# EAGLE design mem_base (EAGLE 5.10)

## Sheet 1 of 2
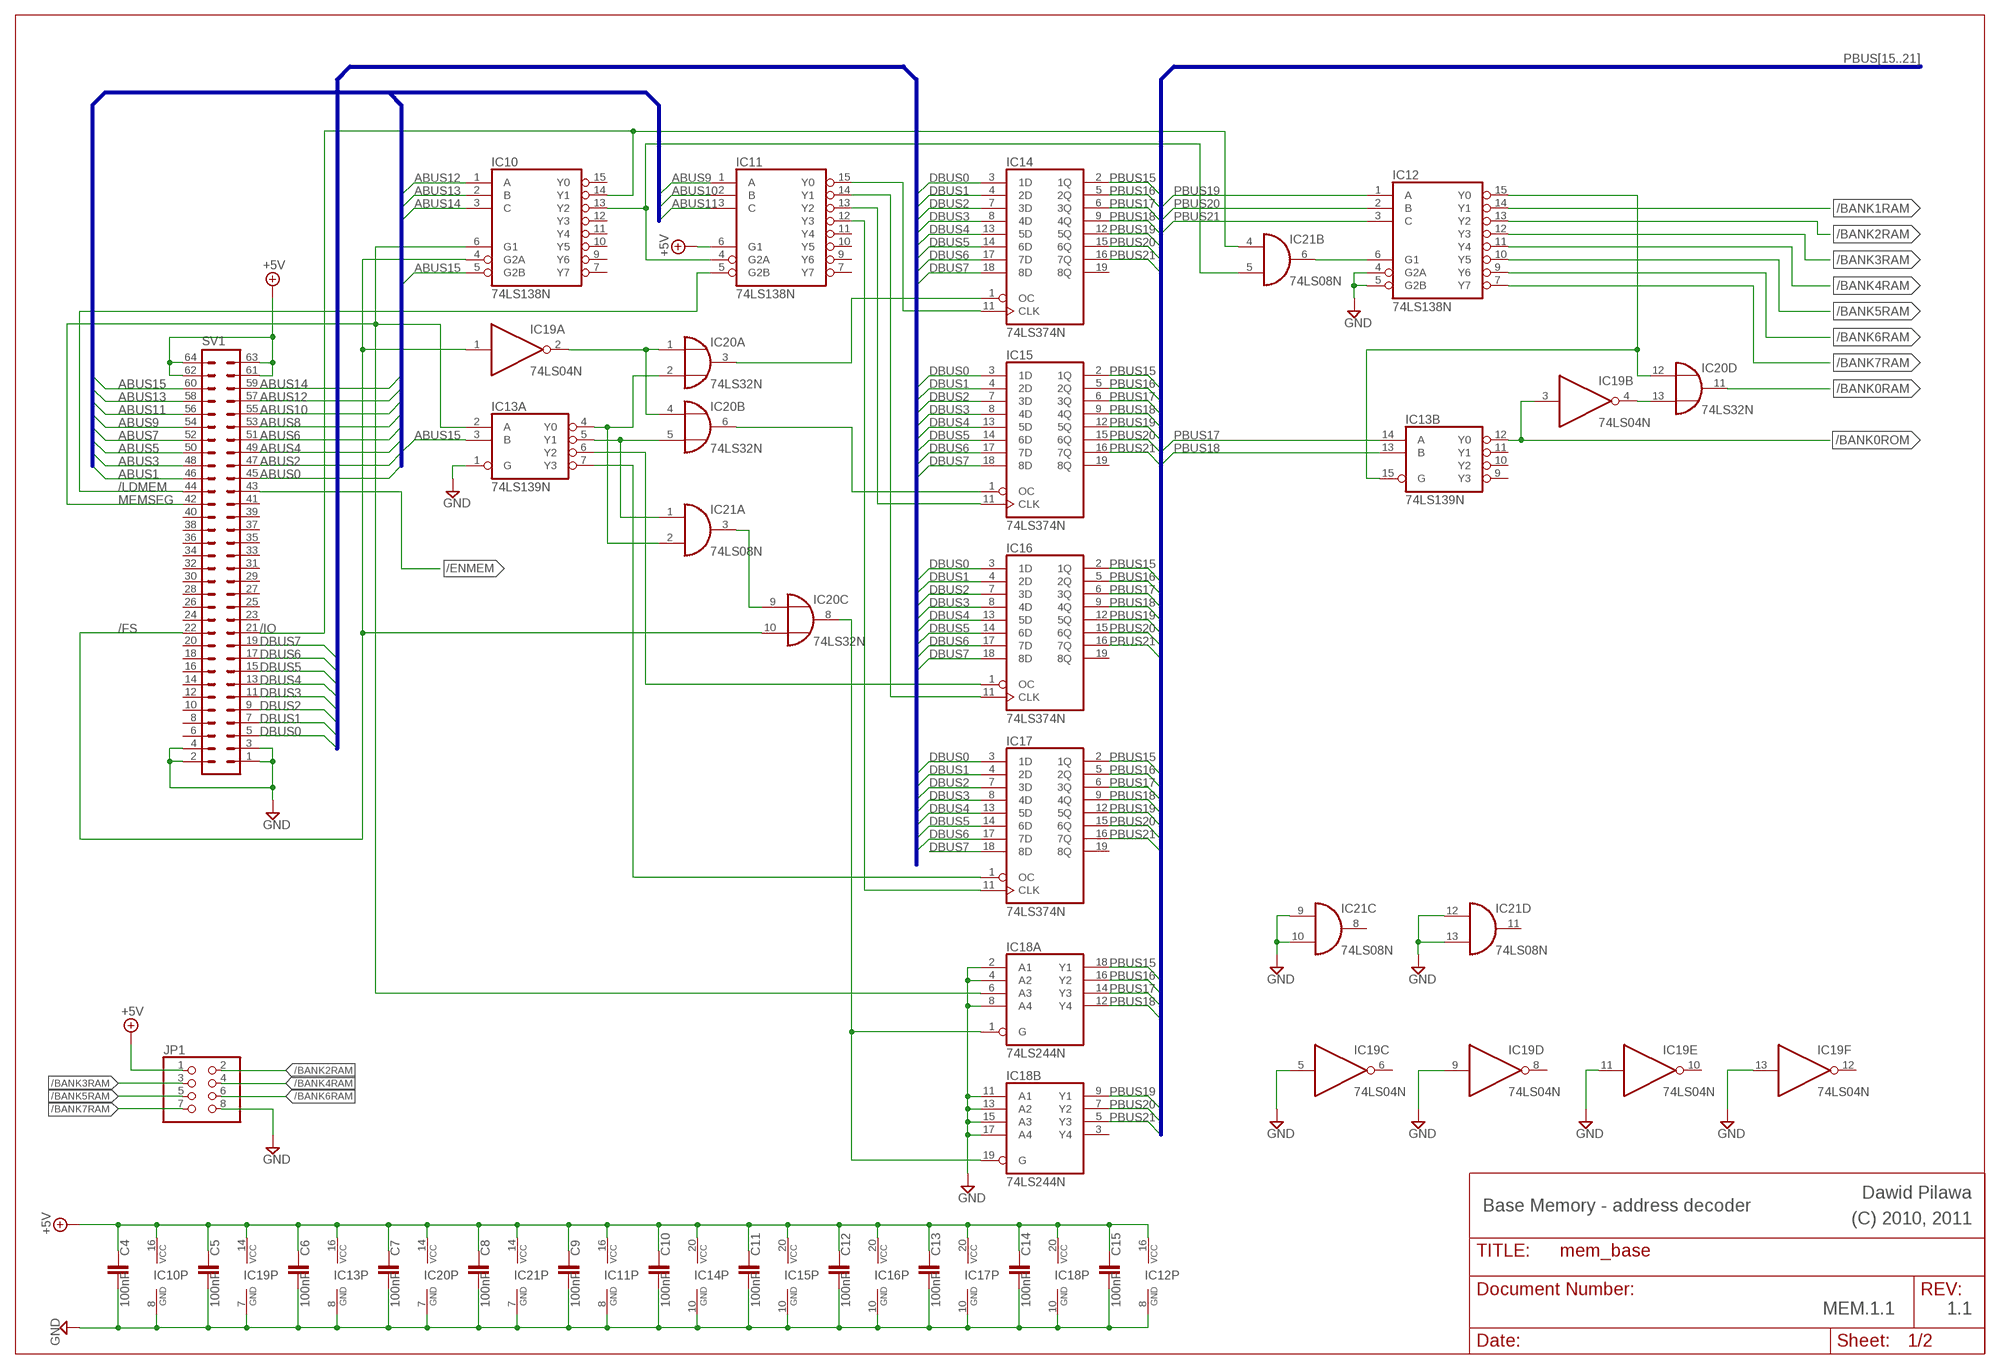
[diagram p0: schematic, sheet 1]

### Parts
C4  100nF  C-EU025-025X050  [C025-025X050]
C5  100nF  C-EU025-025X050  [C025-025X050]
C6  100nF  C-EU025-025X050  [C025-025X050]
C7  100nF  C-EU025-025X050  [C025-025X050]
C8  100nF  C-EU025-025X050  [C025-025X050]
C9  100nF  C-EU025-025X050  [C025-025X050]
C10  100nF  C-EU025-025X050  [C025-025X050]
C11  100nF  C-EU025-025X050  [C025-025X050]
C12  100nF  C-EU025-025X050  [C025-025X050]
C13  100nF  C-EU025-025X050  [C025-025X050]
C14  100nF  C-EU025-025X050  [C025-025X050]
C15  100nF  C-EU025-025X050  [C025-025X050]
IC10  74LS138N  [DIL16]
IC11  74LS138N  [DIL16]
IC12  74LS138N  [DIL16]
IC13  74LS139N  [DIL16]
IC14  74LS374N  [DIL20]
IC15  74LS374N  [DIL20]
IC16  74LS374N  [DIL20]
IC17  74LS374N  [DIL20]
IC18  74LS244N  [DIL20]
IC19  74LS04N  [DIL14]
IC20  74LS32N  [DIL14]
IC21  74LS08N  [DIL14]
JP1  PINHD-2X4  [2X04]
SV1  ML64L  [ML64L]

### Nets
+5V: C4.1 C5.1 C6.1 C7.1 C8.1 C9.1 C10.1 C11.1 C12.1 C13.1 C14.1 C15.1 IC10.16(VCC) IC11.6(G1) IC11.16(VCC) IC12.16(VCC) IC13.16(P:VCC) IC14.20(VCC) IC15.20(VCC) IC16.20(VCC) IC17.20(VCC) IC18.20(P:VCC) IC19.14(P:VCC) IC20.14(P:VCC) IC21.14(P:VCC) JP1.1 SV1.61 SV1.62 SV1.63 SV1.64 ; also sheet 2
/BANK0RAM: IC20.11(D:O) ; also sheet 2
/BANK0ROM: IC13.12(B:Y0) IC19.3(B:I) ; also sheet 2
/BANK1RAM: IC12.14(Y1) ; also sheet 2
/BANK2RAM: IC12.13(Y2) JP1.2
/BANK3RAM: IC12.12(Y3) JP1.3
/BANK4RAM: IC12.11(Y4) JP1.4
/BANK5RAM: IC12.10(Y5) JP1.5
/BANK6RAM: IC12.9(Y6) JP1.6
/BANK7RAM: IC12.7(Y7) JP1.7
/ENMEM: SV1.43 ; also sheet 2
/FS: IC10.4(G2A) IC19.1(A:I) IC20.10(C:I1) SV1.22
/IO: IC10.14(Y1) IC21.4(B:I0) SV1.21
/LDMEM: IC11.5(G2B) SV1.44 ; also sheet 2
ABUS0: SV1.45 ; also sheet 2
ABUS1: SV1.46 ; also sheet 2
ABUS2: SV1.47 ; also sheet 2
ABUS3: SV1.48 ; also sheet 2
ABUS4: SV1.49 ; also sheet 2
ABUS5: SV1.50 ; also sheet 2
ABUS6: SV1.51 ; also sheet 2
ABUS7: SV1.52 ; also sheet 2
ABUS8: SV1.53 ; also sheet 2
ABUS9: IC11.1(A) SV1.54 ; also sheet 2
ABUS10: IC11.2(B) SV1.55 ; also sheet 2
ABUS11: IC11.3(C) SV1.56 ; also sheet 2
ABUS12: IC10.1(A) SV1.57 ; also sheet 2
ABUS13: IC10.2(B) SV1.58 ; also sheet 2
ABUS14: IC10.3(C) SV1.59 ; also sheet 2
ABUS15: IC10.5(G2B) IC13.3(A:B) SV1.60
DBUS0: IC14.3(1D) IC15.3(1D) IC16.3(1D) IC17.3(1D) SV1.5 ; also sheet 2
DBUS1: IC14.4(2D) IC15.4(2D) IC16.4(2D) IC17.4(2D) SV1.7 ; also sheet 2
DBUS2: IC14.7(3D) IC15.7(3D) IC16.7(3D) IC17.7(3D) SV1.9 ; also sheet 2
DBUS3: IC14.8(4D) IC15.8(4D) IC16.8(4D) IC17.8(4D) SV1.11 ; also sheet 2
DBUS4: IC14.13(5D) IC15.13(5D) IC16.13(5D) IC17.13(5D) SV1.13 ; also sheet 2
DBUS5: IC14.14(6D) IC15.14(6D) IC16.14(6D) IC17.14(6D) SV1.15 ; also sheet 2
DBUS6: IC14.17(7D) IC15.17(7D) IC16.17(7D) IC17.17(7D) SV1.17 ; also sheet 2
DBUS7: IC14.18(8D) IC15.18(8D) IC16.18(8D) IC17.18(8D) SV1.19 ; also sheet 2
GND: C4.2 C5.2 C6.2 C7.2 C8.2 C9.2 C10.2 C11.2 C12.2 C13.2 C14.2 C15.2 IC10.8(GND) IC11.8(GND) IC12.4(G2A) IC12.5(G2B) IC12.8(GND) IC13.1(A:G) IC13.8(P:GND) IC14.10(GND) IC15.10(GND) IC16.10(GND) IC17.10(GND) IC18.2(A:A1) IC18.4(A:A2) IC18.8(A:A4) IC18.10(P:GND) IC18.11(B:A1) IC18.13(B:A2) IC18.15(B:A3) IC18.17(B:A4) IC19.5(C:I) IC19.7(P:GND) IC19.9(D:I) IC19.11(E:I) IC19.13(F:I) IC20.7(P:GND) IC21.7(P:GND) IC21.9(C:I0) IC21.10(C:I1) IC21.12(D:I0) IC21.13(D:I1) JP1.8 SV1.1 SV1.2 SV1.3 SV1.4 ; also sheet 2
MEMSEG: IC10.6(G1) IC13.2(A:A) IC18.6(A:A3) SV1.42
N$1: IC10.13(Y2) IC11.4(G2A) IC21.5(B:I1)
N$2: IC19.2(A:O) IC20.1(A:I0) IC20.4(B:I0)
N$3: IC13.4(A:Y0) IC20.2(A:I1) IC21.2(A:I1)
N$4: IC13.5(A:Y1) IC20.5(B:I1) IC21.1(A:I0)
N$5: IC11.15(Y0) IC14.11(CLK)
N$6: IC11.14(Y1) IC16.11(CLK)
N$7: IC11.13(Y2) IC15.11(CLK)
N$8: IC11.12(Y3) IC17.11(CLK)
N$9: IC14.1(OC) IC20.3(A:O)
N$10: IC15.1(OC) IC20.6(B:O)
N$11: IC13.6(A:Y2) IC16.1(OC)
N$12: IC13.7(A:Y3) IC17.1(OC)
N$13: IC18.1(A:G) IC18.19(B:G) IC20.8(C:O)
N$14: IC20.9(C:I0) IC21.3(A:O)
N$15: IC12.15(Y0) IC13.15(B:G) IC20.12(D:I0)
N$16: IC12.6(G1) IC21.6(B:O)
N$17: IC19.4(B:O) IC20.13(D:I1)
PBUS15: IC14.2(1Q) IC15.2(1Q) IC16.2(1Q) IC17.2(1Q) IC18.18(A:Y1) ; also sheet 2
PBUS16: IC14.5(2Q) IC15.5(2Q) IC16.5(2Q) IC17.5(2Q) IC18.16(A:Y2) ; also sheet 2
PBUS17: IC13.14(B:A) IC14.6(3Q) IC15.6(3Q) IC16.6(3Q) IC17.6(3Q) IC18.14(A:Y3) ; also sheet 2
PBUS18: IC13.13(B:B) IC14.9(4Q) IC15.9(4Q) IC16.9(4Q) IC17.9(4Q) IC18.12(A:Y4) ; also sheet 2
PBUS19: IC12.1(A) IC14.12(5Q) IC15.12(5Q) IC16.12(5Q) IC17.12(5Q) IC18.9(B:Y1)
PBUS20: IC12.2(B) IC14.15(6Q) IC15.15(6Q) IC16.15(6Q) IC17.15(6Q) IC18.7(B:Y2)
PBUS21: IC12.3(C) IC14.16(7Q) IC15.16(7Q) IC16.16(7Q) IC17.16(7Q) IC18.5(B:Y3)
Unconnected: IC10.7(Y7) IC10.9(Y6) IC10.10(Y5) IC10.11(Y4) IC10.12(Y3) IC10.15(Y0) IC11.7(Y7) IC11.9(Y6) IC11.10(Y5) IC11.11(Y4) IC13.9(B:Y3) IC13.10(B:Y2) IC13.11(B:Y1) IC14.19(8Q) IC15.19(8Q) IC16.19(8Q) IC17.19(8Q) IC18.3(B:Y4) IC19.6(C:O) IC19.8(D:O) IC19.10(E:O) IC19.12(F:O) IC21.8(C:O) IC21.11(D:O) SV1.6 SV1.8 SV1.10 SV1.12 SV1.14 SV1.16 SV1.18 SV1.20 SV1.23 SV1.24 SV1.25 SV1.26 SV1.27 SV1.28 SV1.29 SV1.30 SV1.31 SV1.32 SV1.33 SV1.34 SV1.35 SV1.36 SV1.37 SV1.38 SV1.39 SV1.40 SV1.41

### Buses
ABUS[0..15]
DBUS[0..7]
PBUS[15..21]

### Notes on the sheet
- Dawid Pilawa
- Base Memory - address decoder | (C) 2010, 2011
- MEM.1.1 | 1.1

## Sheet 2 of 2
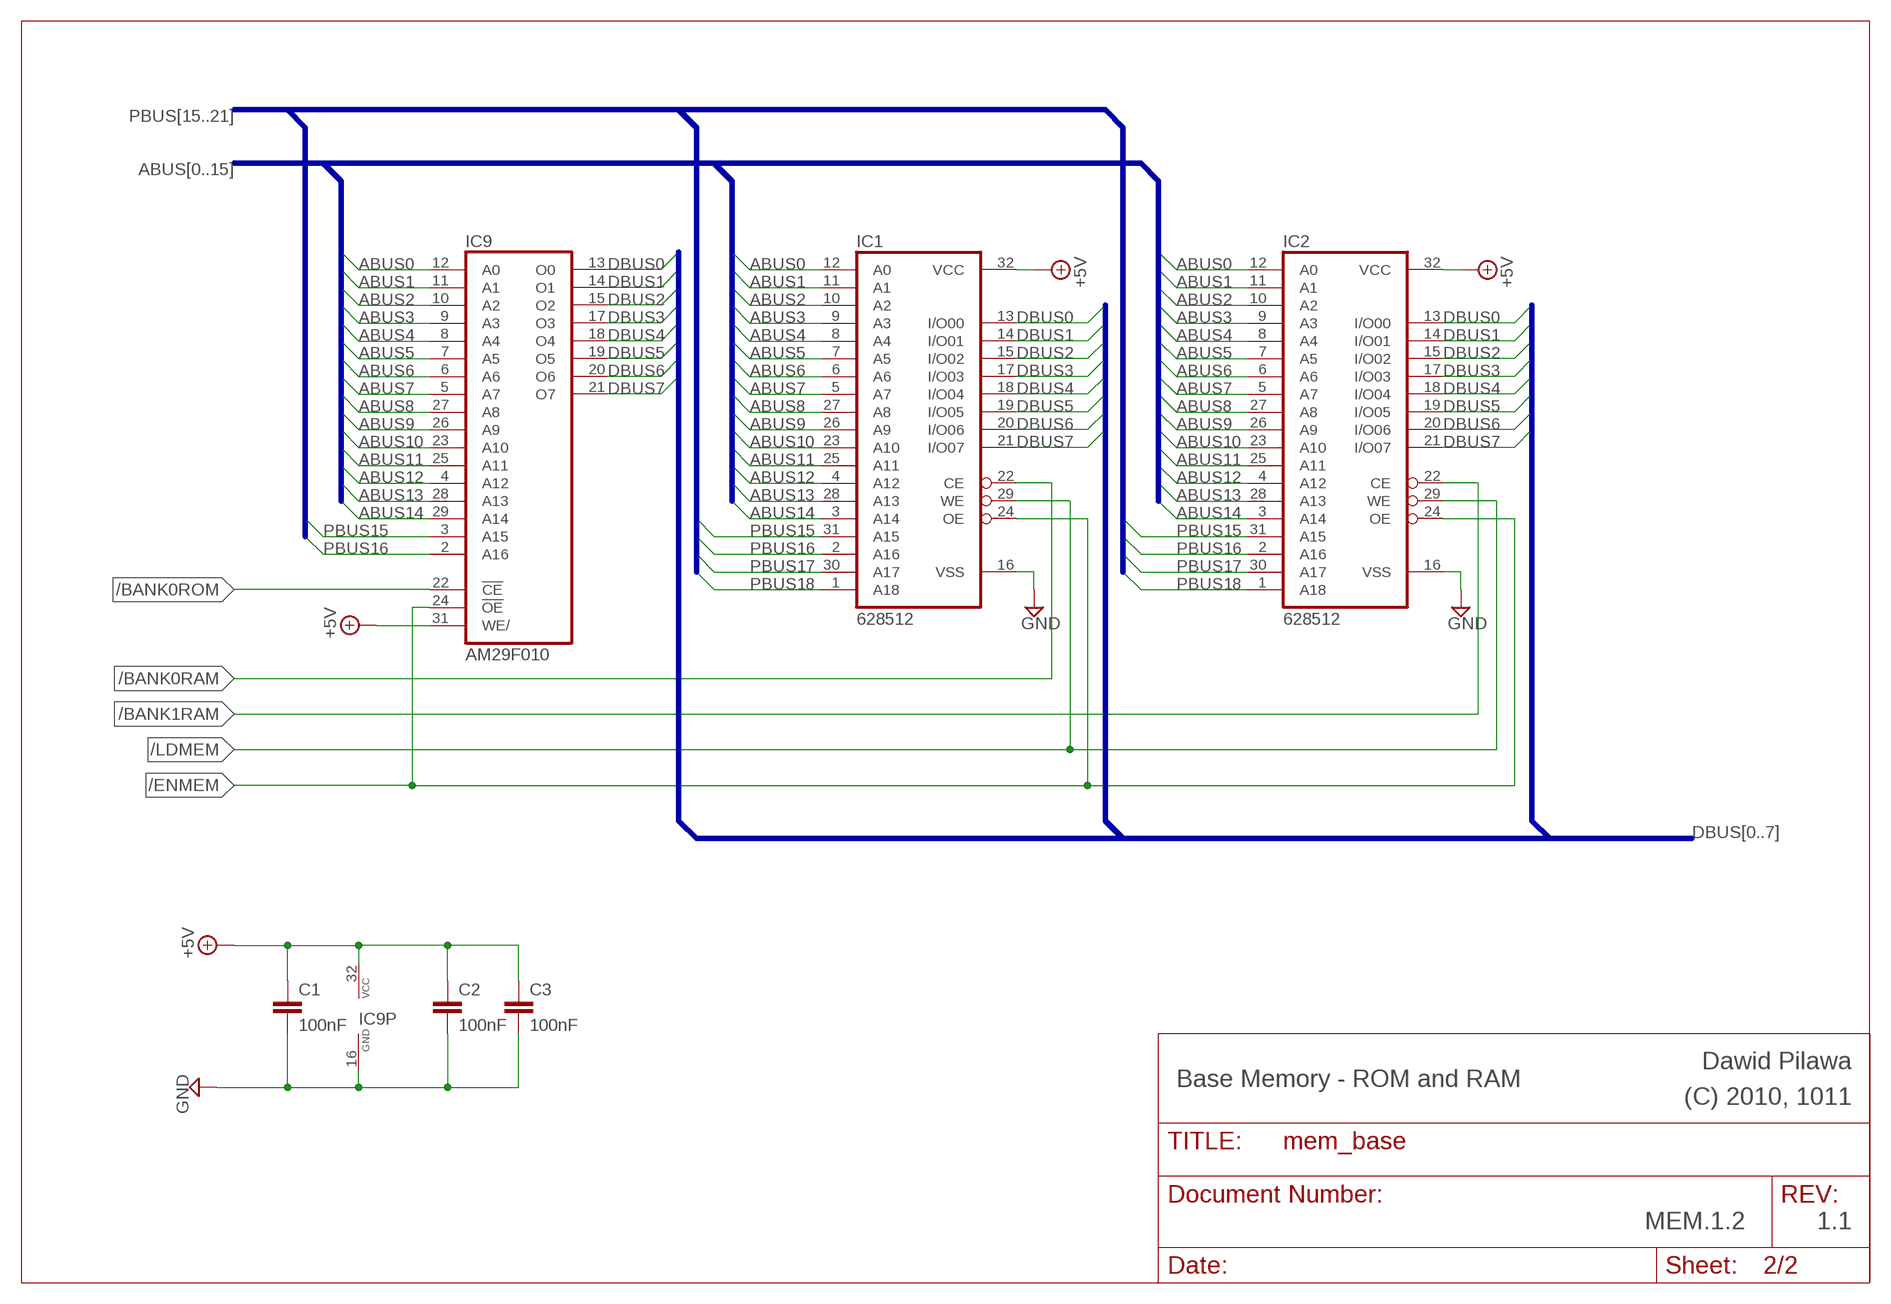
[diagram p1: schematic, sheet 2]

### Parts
C1  100nF  C-EU025-025X050  [C025-025X050]
C2  100nF  C-EU025-025X050  [C025-025X050]
C3  100nF  C-EU025-025X050  [C025-025X050]
IC1  628512  HM628512A_DIL32  [DIL32]
IC2  628512  HM628512A_DIL32  [DIL32]
IC9  AM29F010  [DIL32-6]

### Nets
+5V: C1.1 C2.1 C3.1 IC1.32(VCC) IC2.32(VCC) IC9.31(WE/) IC9.32(VCC) ; also sheet 1
/BANK0RAM: IC1.22(CE) ; also sheet 1
/BANK0ROM: IC9.22(!CE) ; also sheet 1
/BANK1RAM: IC2.22(CE) ; also sheet 1
/ENMEM: IC1.24(OE) IC2.24(OE) IC9.24(!OE) ; also sheet 1
/LDMEM: IC1.29(WE) IC2.29(WE) ; also sheet 1
ABUS0: IC1.12(A0) IC2.12(A0) IC9.12(A0) ; also sheet 1
ABUS1: IC1.11(A1) IC2.11(A1) IC9.11(A1) ; also sheet 1
ABUS2: IC1.10(A2) IC2.10(A2) IC9.10(A2) ; also sheet 1
ABUS3: IC1.9(A3) IC2.9(A3) IC9.9(A3) ; also sheet 1
ABUS4: IC1.8(A4) IC2.8(A4) IC9.8(A4) ; also sheet 1
ABUS5: IC1.7(A5) IC2.7(A5) IC9.7(A5) ; also sheet 1
ABUS6: IC1.6(A6) IC2.6(A6) IC9.6(A6) ; also sheet 1
ABUS7: IC1.5(A7) IC2.5(A7) IC9.5(A7) ; also sheet 1
ABUS8: IC1.27(A8) IC2.27(A8) IC9.27(A8) ; also sheet 1
ABUS9: IC1.26(A9) IC2.26(A9) IC9.26(A9) ; also sheet 1
ABUS10: IC1.23(A10) IC2.23(A10) IC9.23(A10) ; also sheet 1
ABUS11: IC1.25(A11) IC2.25(A11) IC9.25(A11) ; also sheet 1
ABUS12: IC1.4(A12) IC2.4(A12) IC9.4(A12) ; also sheet 1
ABUS13: IC1.28(A13) IC2.28(A13) IC9.28(A13) ; also sheet 1
ABUS14: IC1.3(A14) IC2.3(A14) IC9.29(A14) ; also sheet 1
DBUS0: IC1.13(I/O00) IC2.13(I/O00) IC9.13(O0) ; also sheet 1
DBUS1: IC1.14(I/O01) IC2.14(I/O01) IC9.14(O1) ; also sheet 1
DBUS2: IC1.15(I/O02) IC2.15(I/O02) IC9.15(O2) ; also sheet 1
DBUS3: IC1.17(I/O03) IC2.17(I/O03) IC9.17(O3) ; also sheet 1
DBUS4: IC1.18(I/O04) IC2.18(I/O04) IC9.18(O4) ; also sheet 1
DBUS5: IC1.19(I/O05) IC2.19(I/O05) IC9.19(O5) ; also sheet 1
DBUS6: IC1.20(I/O06) IC2.20(I/O06) IC9.20(O6) ; also sheet 1
DBUS7: IC1.21(I/O07) IC2.21(I/O07) IC9.21(O7) ; also sheet 1
GND: C1.2 C2.2 C3.2 IC1.16(VSS) IC2.16(VSS) IC9.16(GND) ; also sheet 1
PBUS15: IC1.31(A15) IC2.31(A15) IC9.3(A15) ; also sheet 1
PBUS16: IC1.2(A16) IC2.2(A16) IC9.2(A16) ; also sheet 1
PBUS17: IC1.30(A17) IC2.30(A17) ; also sheet 1
PBUS18: IC1.1(A18) IC2.1(A18) ; also sheet 1
Unconnected: IC9.1(NC) IC9.30(NC)

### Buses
ABUS[0..15]
PBUS[15..21]
DBUS[0..7]

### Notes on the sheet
- Dawid Pilawa
- Base Memory - ROM and RAM | (C) 2010, 1011
- MEM.1.2 | 1.1

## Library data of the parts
C1-C15 = rcl:C-EU: CAPACITOR, European symbol
IC1 IC2 = hitachi_sram_hm628512a-series_rev1:HM628512A_DIL32: 4M SRAM 512kword x 8bit
IC9 = am29-memory:AM29F010*: 1-Megabit FLASH MEMORY (128 K x 8 bit) 5 V-only
IC10-IC12 = 74xx-eu:74*138: 3-line to 8-line DECODER/DEMULTIPLEXER
IC13 = 74xx-eu:74*139: Dual 2-line to 4-line DECODER/DEMULTIPLEXER
IC14-IC17 = 74xx-eu:74*374: Octal D type transparent LATCH, edge triggered
IC18 = 74xx-eu:74*244: Octal BUFFER and LINE DRIVER, 3-state
IC19 = 74xx-eu:74*04: Hex INVERTER
IC20 = 74xx-eu:74*32: Quad 2-input OR gate
IC21 = 74xx-eu:74*08: Quad 2-input AND gate
JP1 = pinhead:PINHD-2X4: PIN HEADER
SV1 = con-ml:ML64L: HARTING

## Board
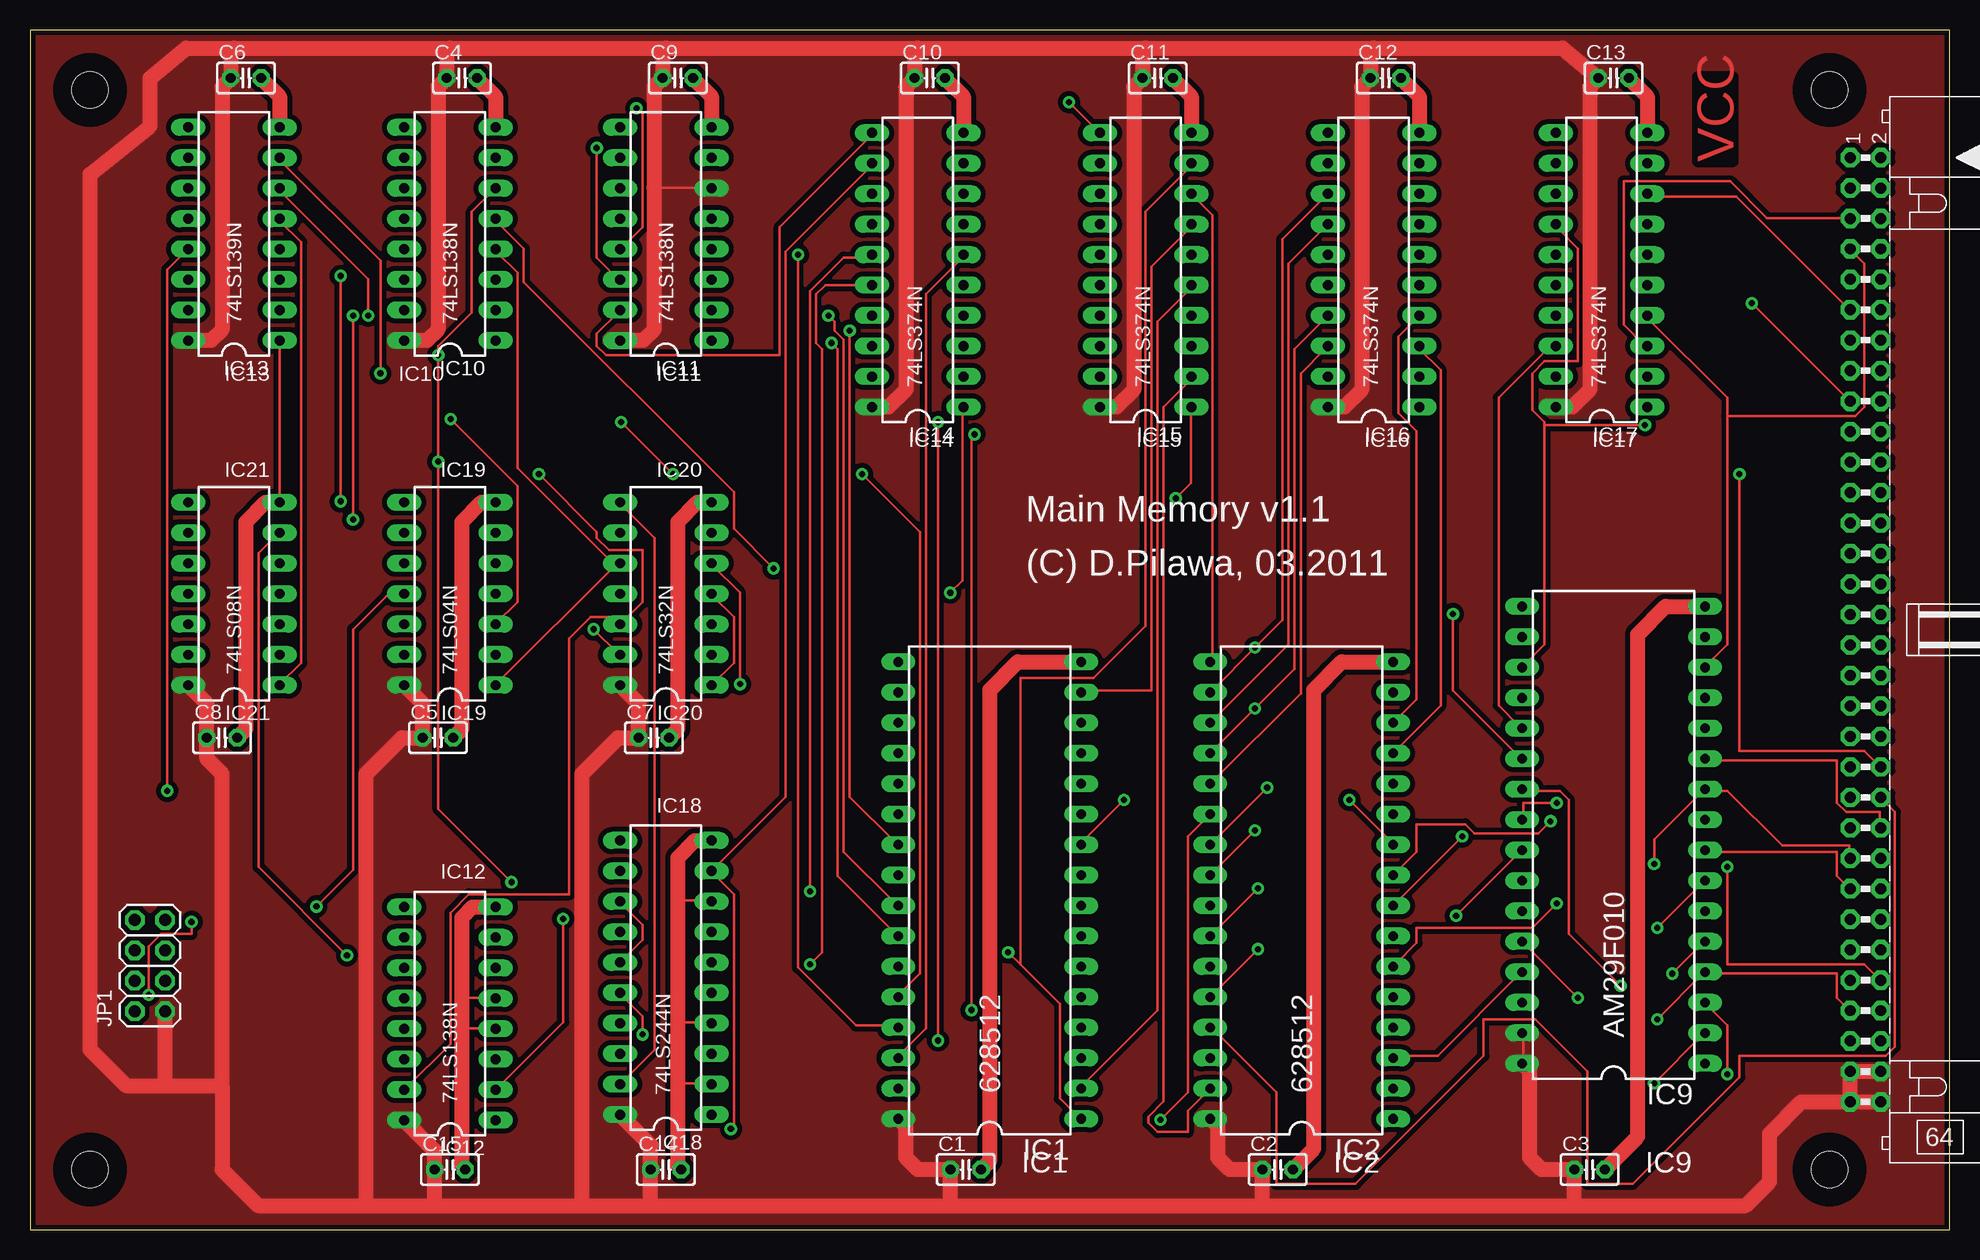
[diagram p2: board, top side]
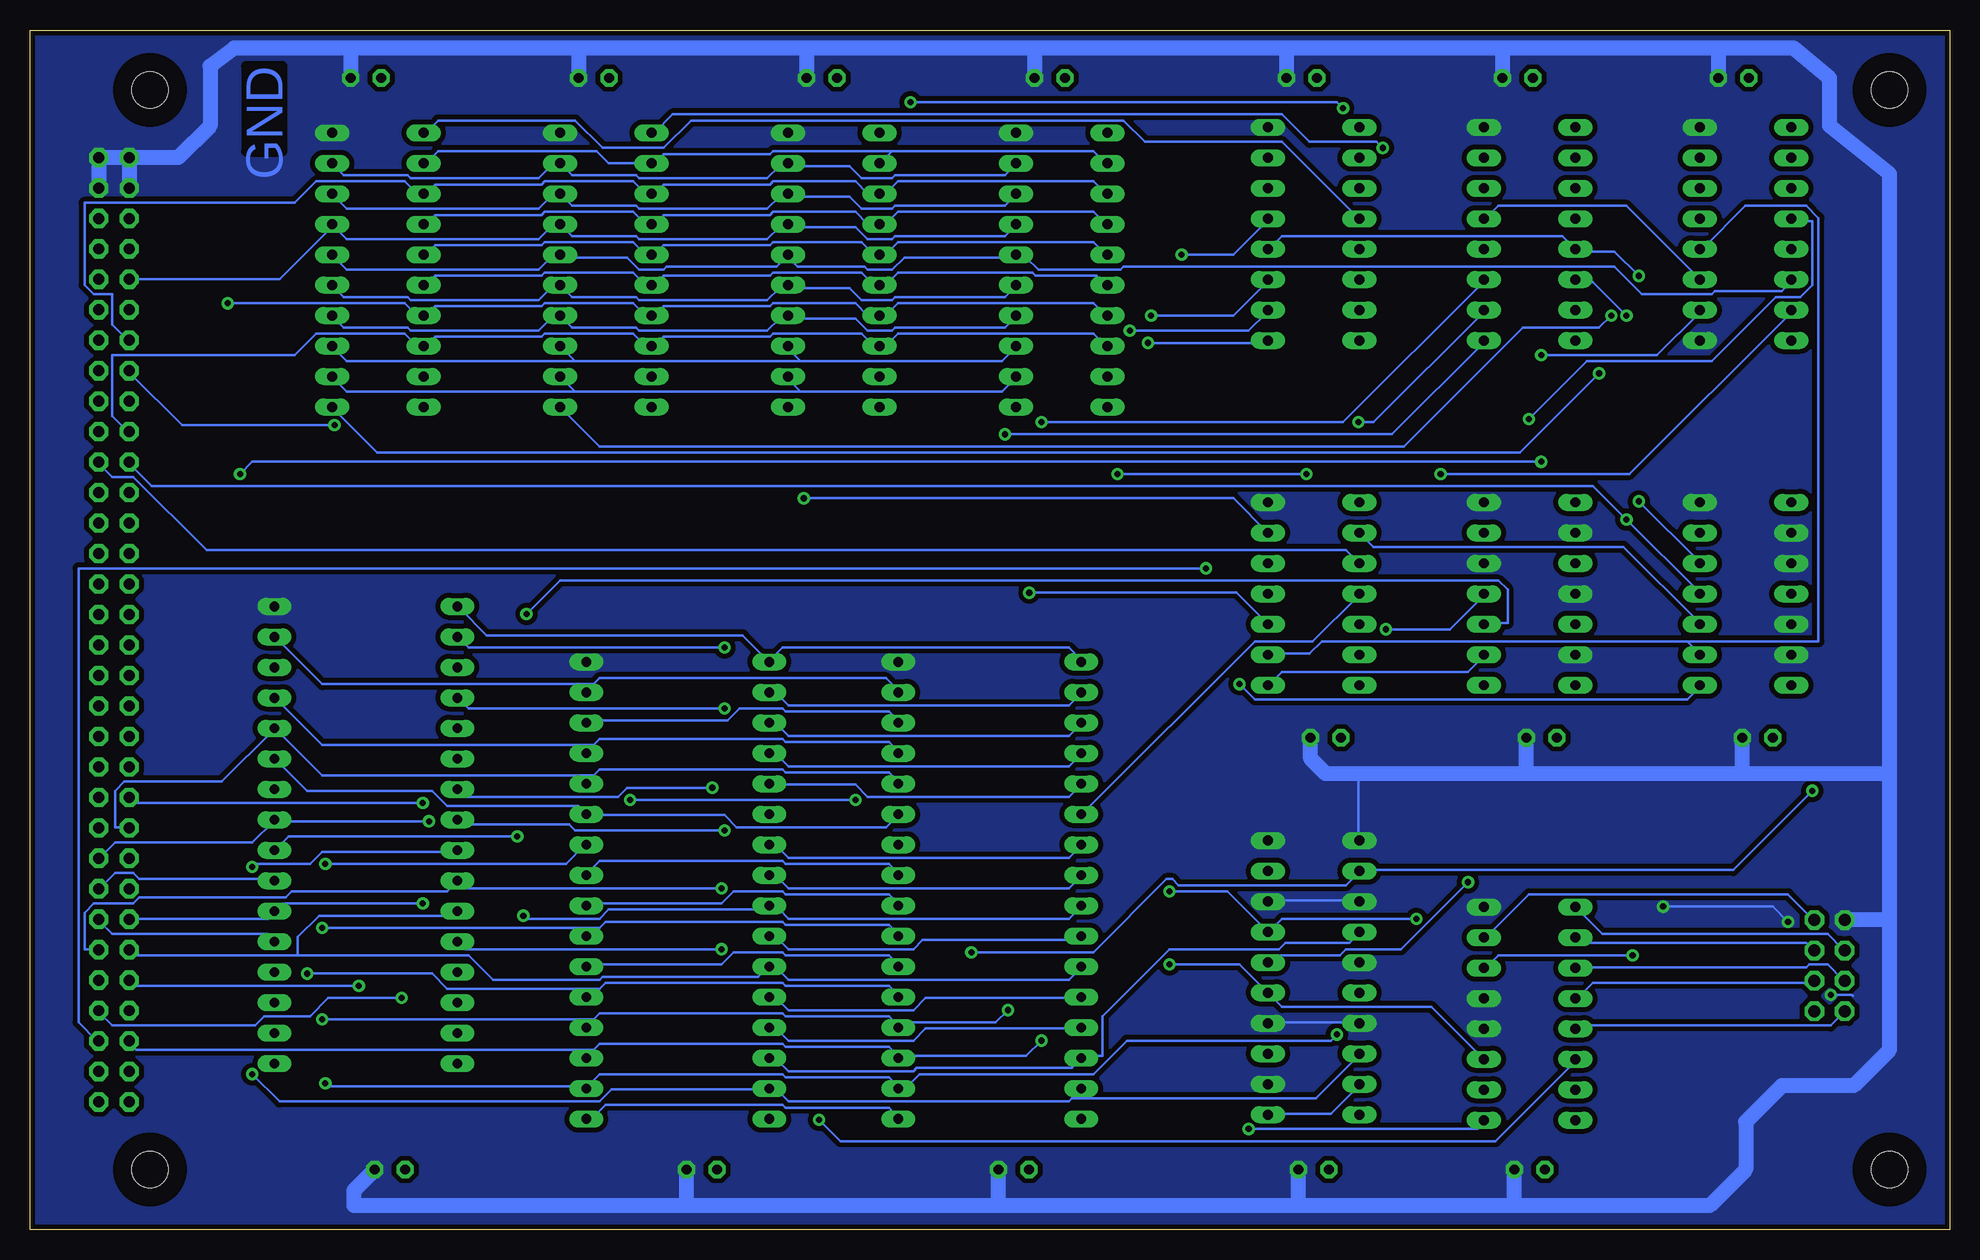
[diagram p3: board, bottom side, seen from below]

Size 160 x 100 mm. Coordinates in mm from the lower left corner, seen from the top.
Outline: 0,0 160,0 160,100 0,100 0,0
Copper layers (1*16): Top 0.035mm / dielectric 1.5mm / Bottom 0.035mm
Design rules "SparkFun": minimum track width 8mil, minimum drill 20mil, track to track 8mil, track to pad 8mil, pad to pad 8mil, via to via 8mil, smd to smd 8mil, copper to edge 10mil, drill to drill 8mil, minimum pad ring 12mil, minimum via ring 10mil, stop-mask expansion 4mil, vias tented up to drill 25mil, thermal gap 10mil
Holes 3 mm at 5,95 5,5 150,5 150,95
tRestrict: area 147.8,2.8 to 152.2,7.2; area 147.8,92.8 to 152.2,97.2; area 2.8,92.8 to 7.2,97.2; area 2.8,2.8 to 7.2,7.2
bRestrict: area 2.8,2.8 to 7.2,7.2; area 147.8,2.8 to 152.2,7.2; area 147.8,92.8 to 152.2,97.2; area 2.8,92.8 to 7.2,97.2

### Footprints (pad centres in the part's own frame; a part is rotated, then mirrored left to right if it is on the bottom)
C025-025X050 = drill 0.813 octagon: 1 -1.27,0; 2 1.27,0
DIL32 = drill 0.813 long: 1 -17.78,-7.62; 2 -15.24,-7.62; 3 -12.7,-7.62; 4 -10.16,-7.62; 5 -7.62,-7.62; 6 -5.08,-7.62; 7 -2.54,-7.62; 8 0,-7.62; 9 2.54,-7.62; 10 5.08,-7.62; 11 7.62,-7.62; 12 10.16,-7.62; 13 12.7,-7.62; 14 15.24,-7.62; 15 17.78,-7.62; 16 20.32,-7.62; 17 20.32,7.62; 18 17.78,7.62; 19 15.24,7.62; 20 12.7,7.62; 21 10.16,7.62; 22 7.62,7.62; 23 5.08,7.62; 24 2.54,7.62; 25 0,7.62; 26 -2.54,7.62; 27 -5.08,7.62; 28 -7.62,7.62; 29 -10.16,7.62; 30 -12.7,7.62; 31 -15.24,7.62; 32 -17.78,7.62
DIL32-6 = drill 0.813 long: 1 -17.78,-7.62; 2 -15.24,-7.62; 3 -12.7,-7.62; 4 -10.16,-7.62; 5 -7.62,-7.62; 6 -5.08,-7.62; 7 -2.54,-7.62; 8 0,-7.62; 9 2.54,-7.62; 10 5.08,-7.62; 11 7.62,-7.62; 12 10.16,-7.62; 13 12.7,-7.62; 14 15.24,-7.62; 15 17.78,-7.62; 16 20.32,-7.62; 17 20.32,7.62; 18 17.78,7.62; 19 15.24,7.62; 20 12.7,7.62; 21 10.16,7.62; 22 7.62,7.62; 23 5.08,7.62; 24 2.54,7.62; 25 0,7.62; 26 -2.54,7.62; 27 -5.08,7.62; 28 -7.62,7.62; 29 -10.16,7.62; 30 -12.7,7.62; 31 -15.24,7.62; 32 -17.78,7.62
DIL16 = drill 0.813 long: 1 -8.89,-3.81; 2 -6.35,-3.81; 3 -3.81,-3.81; 4 -1.27,-3.81; 5 1.27,-3.81; 6 3.81,-3.81; 7 6.35,-3.81; 8 8.89,-3.81; 9 8.89,3.81; 10 6.35,3.81; 11 3.81,3.81; 12 1.27,3.81; 13 -1.27,3.81; 14 -3.81,3.81; 15 -6.35,3.81; 16 -8.89,3.81
DIL20 = drill 0.813 long: 1 -11.43,-3.81; 2 -8.89,-3.81; 3 -6.35,-3.81; 4 -3.81,-3.81; 5 -1.27,-3.81; 6 1.27,-3.81; 7 3.81,-3.81; 8 6.35,-3.81; 9 8.89,-3.81; 10 11.43,-3.81; 11 11.43,3.81; 12 8.89,3.81; 13 6.35,3.81; 14 3.81,3.81; 15 1.27,3.81; 16 -1.27,3.81; 17 -3.81,3.81; 18 -6.35,3.81; 19 -8.89,3.81; 20 -11.43,3.81
DIL14 = drill 0.813 long: 1 -7.62,-3.81; 2 -5.08,-3.81; 3 -2.54,-3.81; 4 0,-3.81; 5 2.54,-3.81; 6 5.08,-3.81; 7 7.62,-3.81; 8 7.62,3.81; 9 5.08,3.81; 10 2.54,3.81; 11 0,3.81; 12 -2.54,3.81; 13 -5.08,3.81; 14 -7.62,3.81
2X04 = drill 1.016 octagon: 1 -3.81,-1.27; 2 -3.81,1.27; 3 -1.27,-1.27; 4 -1.27,1.27; 5 1.27,-1.27; 6 1.27,1.27; 7 3.81,-1.27; 8 3.81,1.27
ML64L = drill 0.914 pad 1.6 octagon: 1 -39.37,-1.27; 2 -39.37,1.27; 3 -36.83,-1.27; 4 -36.83,1.27; 5 -34.29,-1.27; 6 -34.29,1.27; 7 -31.75,-1.27; 8 -31.75,1.27; 9 -29.21,-1.27; 10 -29.21,1.27; 11 -26.67,-1.27; 12 -26.67,1.27; 13 -24.13,-1.27; 14 -24.13,1.27; 15 -21.59,-1.27; 16 -21.59,1.27; 17 -19.05,-1.27; 18 -19.05,1.27; 19 -16.51,-1.27; 20 -16.51,1.27; 21 -13.97,-1.27; 22 -13.97,1.27; 23 -11.43,-1.27; 24 -11.43,1.27; 25 -8.89,-1.27; 26 -8.89,1.27; 27 -6.35,-1.27; 28 -6.35,1.27; 29 -3.81,-1.27; 30 -3.81,1.27; 31 -1.27,-1.27; 32 -1.27,1.27; 33 1.27,-1.27; 34 1.27,1.27; 35 3.81,-1.27; 36 3.81,1.27; 37 6.35,-1.27; 38 6.35,1.27; 39 8.89,-1.27; 40 8.89,1.27; 41 11.43,-1.27; 42 11.43,1.27; 43 13.97,-1.27; 44 13.97,1.27; 45 16.51,-1.27; 46 16.51,1.27; 47 19.05,-1.27; 48 19.05,1.27; 49 21.59,-1.27; 50 21.59,1.27; 51 24.13,-1.27; 52 24.13,1.27; 53 26.67,-1.27; 54 26.67,1.27; 55 29.21,-1.27; 56 29.21,1.27; 57 31.75,-1.27; 58 31.75,1.27; 59 34.29,-1.27; 60 34.29,1.27; 61 36.83,-1.27; 62 36.83,1.27; 63 39.37,-1.27; 64 39.37,1.27

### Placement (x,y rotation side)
C1  78,5 0 top
C2  104,5 0 top
C3  130,5 0 top
C4  36,96 0 top
C5  34,41 0 top
C6  18,96 0 top
C7  52,41 0 top
C8  16,41 0 top
C9  54,96 0 top
C10  75,96 0 top
C11  94,96 0 top
C12  113,96 0 top
C13  132,96 0 top
C14  53,5 0 top
C15  35,5 0 top
IC1  80,27 90 top
IC2  106,27 90 top
IC9  132,31.62 90 top
IC10  35,83 90 top
IC11  53,83 90 top
IC12  35,18 90 top
IC13  17,83 90 top
IC14  74,80 90 top
IC15  93,80 90 top
IC16  112,80 90 top
IC17  131,80 90 top
IC18  53,21 90 top
IC19  35,53 90 top
IC20  53,53 90 top
IC21  17,53 90 top
JP1  10,22 90 top
SV1  153,50 270 top

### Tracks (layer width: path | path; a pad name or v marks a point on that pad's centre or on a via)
+5V
  Top 0.203: IC9.31 124.46,16.26 124.46,14.22 IC9.32 | IC11.6 56.64,86.87 52,86.87
  Top 1.27: SV1.63 SV1.64 | SV1.63 SV1.61 SV1.62 | SV1.63 147.63,10.63 145,8 145,4 143,2 129,2 | 28,2 19,2 16,5 16,12 | 28,2 34,2 | 34,2 46,2 | 46,2 52,2 | 52,2 77,2 | 77,2 103,2 | 103,2 129,2 | 11,12 8,12 5,15 5,88 10,92 10,96 13,98.49 17,98.49 | 11,12 16,12 | 17,98.49 35,98.49 | 35,98.49 53,98.49 | 53,98.49 74,98.49 | 74,98.49 93,98.49 | 93,98.49 112,98.49 | 112,98.49 127.73,98.49 C13.1 130,95.27 130,70 128.57,68.57 IC17.20 | 112,98.49 111.73,98.22 C12.1 111,95.27 111,70 109.57,68.57 IC16.20 | 93,98.49 92.73,98.22 C11.1 92,95.27 92,70 90.57,68.57 IC15.20 | 74,98.49 73.73,98.22 C10.1 73,95.27 73,70 71.57,68.57 IC14.20 | 53,98.49 52.73,98.22 C9.1 52,95.27 52,86.87 52,75 51.11,74.11 IC11.16 | 35,98.49 34.73,98.22 C4.1 34,95.27 34,75 33.11,74.11 IC10.16 | 17,98.49 16.73,98.22 C6.1 16,95.27 16,75 15.11,74.11 IC13.16 | JP1.1 11.27,12.27 11,12 | 34,2 33.73,2.27 C15.1 33.73,6.57 IC12.16 | IC18.20 51.73,7.03 C14.1 51.73,2.27 52,2 | 77,2 76.73,2.27 C1.1 74,5 73,6 73,8.6 IC1.32 | 103,2 102.73,2.27 C2.1 100,5 99,6 99,8.6 IC2.32 | 129,2 128.73,2.27 C3.1 126,5 125,6 125,13.22 IC9.32 | 28,2 28,38 31,41 C5.1 32.73,43.84 IC19.14 | 46,2 46,38 49,41 C7.1 50.73,43.84 IC20.14 | 16,12 16,38 14.73,39.27 C8.1 14.73,43.84 IC21.14
  pour Top (isolate 0.406, no thermals): 0,100 160,100 160,0 0,0
/BANK0RAM
  Bottom 0.203: IC20.11 49.28,52.83 53.09,49.02 57.91,49.02 72.14,34.8 IC1.22
/BANK0ROM  (via drill 0.51)
  Top 0.203: v35.05,67.56 40.64,61.98 40.64,52.32 38.86,50.55 IC19.3 | v118.62,51.31 118.62,44.96 124.21,39.37 IC9.22
  Bottom 0.203: v35.05,67.56 30.23,72.39 19.81,72.39 14.48,77.72 12.45,77.72 11.43,78.74 11.43,84.07 12.95,84.07 IC13.12 | v118.62,51.31 115.82,54.1 37.59,54.1 36.83,53.34 36.83,50.55 38.61,50.55 IC19.3
/BANK1RAM  (via drill 0.51)
  Top 0.203: v94.23,9.14 96.52,11.43 96.52,32.77 98.3,34.54 IC2.22
  Bottom 0.203: v94.23,9.14 92.46,7.37 37.85,7.37 31.24,13.97 IC12.14
/BANK2RAM
  Bottom 0.203: IC12.13 30.99,16.76 30.73,17.02 9.91,17.02 8.89,18.03 JP1.2
/BANK3RAM
  Bottom 0.203: IC12.12 30.99,19.3 29.72,20.57 11.43,20.57 JP1.3
/BANK4RAM
  Bottom 0.203: IC12.11 30.99,21.84 11.94,21.84 11.68,22.1 10.16,22.1 8.89,20.83 JP1.4
/BANK5RAM
  Bottom 0.203: IC12.10 30.99,24.13 30.73,23.88 11.94,23.88 11.43,23.37 JP1.5
/BANK6RAM
  Bottom 0.203: IC12.9 30.99,26.67 28.96,24.64 10.16,24.64 8.89,23.37 JP1.6
/BANK7RAM
  Bottom 0.203: IC12.7 38.61,24.38 35.05,27.94 13.46,27.94 11.43,25.91 JP1.7
/ENMEM  (via drill 0.51)
  Top 0.203: v102.11,33.27 98.55,29.72 IC2.24 | v127.25,35.56 124.46,35.56 124.46,34.29 IC9.24
  Bottom 0.203: IC1.24 72.39,29.46 73.41,28.45 96.77,28.45 97.79,29.46 98.3,29.46 IC2.24 | v102.11,33.27 114.55,33.27 115.06,33.78 123.95,33.78 124.21,34.04 IC9.24 | v127.25,35.56 151.38,35.56 151.64,35.81 SV1.43
/FS
  Top 0.203: 48.77,55.37 49.02,55.63 IC20.10 48.77,55.37 | 48.77,55.37 38.86,45.47 IC19.1 | 48.77,55.37 40.64,63.5 40.64,79.76 38.86,81.53 IC10.4
  Bottom 0.203: SV1.22 154.18,63.75 153.16,62.74 151.38,62.74 145.29,56.64 50.29,56.64 IC20.10
/IO  (via drill 0.51)
  Top 0.203: v26.92,59.18 v26.92,76.2
  Bottom 0.203: v26.92,76.2 29.72,78.99 30.99,78.99 IC10.14 | IC21.4 20.83,53.09 v26.92,59.18 29.72,61.98 149.86,61.98 151.64,63.75 SV1.21
/LDMEM  (via drill 0.51)
  Top 0.203: v64.01,81.28 64.01,21.84 68.83,17.02 72.14,17.02 IC1.29 | SV1.44 154.43,35.81 155.45,34.8 155.45,15.24 154.69,14.48 142.49,14.48 142.49,12.7 133.6,3.81 129.79,3.81 129.79,13.21 125.48,17.53 121.16,17.53 121.16,14.48 110.49,3.81 103.89,3.81 103.89,11.43 98.55,16.76 IC2.29
  Bottom 0.203: IC1.29 72.39,16.76 85.34,16.76 86.36,15.75 96.77,15.75 97.79,16.76 98.3,16.76 IC2.29 | v64.01,81.28 59.69,81.28 56.9,84.07 IC11.5
ABUS0
  Bottom 0.203: SV1.45 151.89,33.53 152.91,33.53 152.91,36.58 152.15,37.34 144.02,37.34 139.7,41.66 IC9.12 139.45,41.66 135.64,37.85 113.03,37.85 | 113.03,37.85 113.54,37.34 IC2.12 113.03,37.85 | 113.03,37.85 112.52,38.35 97.28,38.35 97.03,38.1 88.39,38.1 87.63,37.34 IC1.12
ABUS1
  Top 0.203: IC9.11 139.7,39.12 150.62,39.12 150.62,35.56 151.38,34.8 154.18,34.8 154.18,33.53 SV1.46
  Bottom 0.203: IC1.11 87.63,34.54 88.65,33.53 101.09,33.53 102.11,34.54 113.54,34.54 IC2.11 113.79,34.8 114.3,35.31 125.22,35.31 126.49,36.58 136.91,36.58 139.45,39.12 IC9.11
ABUS2  (via drill 0.51)
  Top 0.203: SV1.47 151.64,30.99 151.64,32 146.05,32 141.48,36.58 139.7,36.58 IC9.10 139.45,36.58 135.38,32.51 v135.38,30.48 | v91.19,35.81 87.63,32.26 IC1.10 | v109.98,35.81 113.54,32.26 IC2.10
  Bottom 0.203: v91.19,35.81 v109.98,35.81 | v135.38,30.48 115.32,30.48 113.79,32 IC2.10
ABUS3  (via drill 0.51)
  Top 0.203: v126.75,34.04 125.73,33.02 120.4,33.02 119.63,33.78 115.57,33.78 115.57,31.5 113.79,29.72 IC2.9
  Bottom 0.203: SV1.48 154.18,30.99 152.91,32.26 141.48,32.26 139.7,34.04 IC9.9 139.45,34.04 v126.75,34.04 | IC1.9 87.63,29.72 88.39,30.48 97.03,30.48 97.28,30.73 112.52,30.73 113.54,29.72 IC2.9
ABUS4  (via drill 0.51)
  Top 0.203: IC9.8 139.7,31.5 150.62,31.5 150.62,29.46 151.64,28.45 SV1.49 | v119.38,32.77 113.79,27.18 IC2.8
  Bottom 0.203: IC1.8 87.63,27.18 88.39,27.94 97.03,27.94 97.28,28.19 101.35,28.19 102.36,27.18 113.54,27.18 IC2.8 | v119.38,32.77 138.43,32.77 139.45,31.75 IC9.8
ABUS5  (via drill 0.51)
  Top 0.203: v135.64,25.15 139.45,28.96 IC9.7
  Bottom 0.203: IC9.7 139.7,29.21 150.88,29.21 151.38,29.72 152.91,29.72 154.18,28.45 SV1.50 | 112.52,25.15 113.03,24.64 113.54,24.64 IC2.7 | 112.52,25.15 112.01,25.65 97.28,25.65 97.03,25.4 88.39,25.4 87.63,24.64 IC1.7 | 112.52,25.15 v135.64,25.15
ABUS6  (via drill 0.51)
  Top 0.203: v127.25,27.18 125.22,25.15 115.57,25.15 115.57,23.88 113.79,22.1 IC2.6
  Bottom 0.203: SV1.51 151.64,25.91 140.21,25.91 139.7,26.42 IC9.6 139.45,26.67 138.94,27.18 v127.25,27.18 | IC1.6 87.63,22.1 88.39,22.86 97.03,22.86 97.28,23.11 101.35,23.11 102.36,22.1 113.54,22.1 IC2.6
ABUS7  (via drill 0.51)
  Top 0.203: v136.91,21.34 139.45,23.88 IC9.5
  Bottom 0.203: IC9.5 139.7,24.13 140.21,24.64 153.16,24.64 154.18,25.65 SV1.52 | 112.52,20.07 113.03,19.56 113.54,19.56 IC2.5 | 112.52,20.07 112.01,20.57 97.28,20.57 97.03,20.32 88.39,20.32 87.63,19.56 IC1.5 | v136.91,21.34 126.49,21.34 125.22,20.07 112.52,20.07
ABUS8
  Bottom 0.203: IC1.27 72.39,21.84 73.41,20.83 96.77,20.83 97.79,21.84 98.3,21.84 IC2.27 98.55,21.84 99.31,21.08 112.27,21.08 112.52,20.83 121.41,20.83 123.44,22.86 137.67,22.86 | 137.67,22.86 137.67,24.38 135.89,26.16 124.71,26.16 124.46,26.42 IC9.27 | 137.67,22.86 151.38,22.86 151.64,23.11 SV1.53
ABUS9  (via drill 0.51)
  Top 0.203: v66.8,73.91 67.31,73.41 67.31,29.46 72.14,24.64 IC1.26 | v102.36,28.45 98.55,24.64 IC2.26
  Bottom 0.203: SV1.54 154.43,23.37 155.45,23.37 155.45,26.42 154.69,27.18 151.38,27.18 150.88,27.69 138.68,27.69 138.18,28.19 125.22,28.19 124.46,28.96 IC9.26 124.21,28.96 123.7,28.45 v102.36,28.45 | IC1.26 72.39,24.38 72.64,24.13 85.6,24.13 86.36,23.37 96.77,23.37 97.79,24.38 98.3,24.38 IC2.26 | v66.8,73.91 56.9,73.91 IC11.1
ABUS10  (via drill 0.51)
  Top 0.203: v68.33,74.93 68.33,36.07 72.14,32.26 IC1.23 | v103.12,36.83 98.55,32.26 IC2.23 | v132.59,20.32 128.27,24.64 128.27,35.81 127.51,36.58 124.46,36.58 IC9.23
  Bottom 0.203: IC1.23 72.39,32 73.41,30.99 96.77,30.99 97.79,32 98.3,32 IC2.23 | v68.33,74.93 58.42,74.93 56.9,76.45 IC11.2 | v103.12,36.83 110.24,36.83 111,36.07 123.7,36.07 124.21,36.58 IC9.23 | v132.59,20.32 151.38,20.32 151.64,20.57 SV1.55
ABUS11  (via drill 0.51)
  Top 0.203: v66.55,76.2 67.06,75.69 67.06,74.93 67.82,74.17 67.82,31.5 72.14,27.18 IC1.25 | v118.87,26.16 124.21,31.5 IC9.25 | v141.48,30.23 141.48,22.1 152.91,22.1 154.18,20.83 SV1.56
  Bottom 0.203: 97.54,26.67 97.79,26.92 98.3,26.92 IC2.25 97.54,26.67 | 97.54,26.67 96.77,25.91 73.41,25.91 72.39,26.92 IC1.25 | v66.55,76.2 59.69,76.2 56.9,78.99 IC11.3 | v118.87,26.16 118.62,25.91 112.52,25.91 111.76,26.67 97.54,26.67 | v141.48,30.23 141.22,30.48 136.65,30.48 135.64,31.5 124.46,31.5 IC9.25
ABUS12  (via drill 0.51)
  Top 0.203: SV1.57 151.64,18.29 150.62,19.3 150.62,21.34 139.7,21.34 IC9.4 139.45,21.34 v135.64,17.53 | v78.74,66.29 78.49,66.04 v78.49,18.29
  Bottom 0.203: 87.88,17.27 88.39,17.78 97.03,17.78 97.28,18.03 112.52,18.03 113.03,17.53 | 87.88,17.27 87.63,17.02 IC1.4 87.88,17.27 | 113.03,17.53 113.54,17.02 IC2.4 113.03,17.53 | v78.74,66.29 46.48,66.29 38.86,73.91 IC10.1 | v78.49,18.29 79.5,17.27 87.88,17.27 | 113.03,17.53 v135.64,17.53
ABUS13  (via drill 0.51)
  Top 0.203: v53.59,62.99 v49.28,67.31 | v69.34,62.99 74.17,58.17 74.17,21.34 72.39,19.56 IC1.28 | v102.36,23.37 98.55,19.56 IC2.28 | v129.03,19.3 124.46,23.88 IC9.28
  Bottom 0.203: IC1.28 72.39,19.3 85.34,19.3 86.36,18.29 96.77,18.29 97.79,19.3 98.3,19.3 IC2.28 | v49.28,67.31 48.01,67.31 38.86,76.45 IC10.2 | v69.34,62.99 v53.59,62.99 | v102.36,23.37 123.7,23.37 124.21,23.88 IC9.28 | v129.03,19.3 135.13,19.3 136.65,17.78 140.46,17.78 141.22,17.02 153.16,17.02 154.18,18.03 SV1.58
ABUS14  (via drill 0.51)
  Top 0.203: v75.69,15.75 v75.69,67.31 | IC9.29 124.21,21.34 117.35,14.48 113.79,14.48 IC2.3
  Bottom 0.203: 113.03,14.99 113.54,14.48 IC2.3 113.03,14.99 | 113.03,14.99 112.52,15.49 97.28,15.49 97.03,15.24 88.39,15.24 87.63,14.48 IC1.3 87.38,14.48 76.96,14.48 v75.69,15.75 | v75.69,67.31 50.55,67.31 38.86,78.99 IC10.3 | 113.03,14.99 151.13,14.99 151.64,15.49 SV1.59
ABUS15  (via drill 0.51)
  Top 0.203: v61.98,55.12 58.67,58.42 58.67,61.47 41.15,78.99 41.15,81.79 38.86,84.07 IC10.5
  Bottom 0.203: IC13.3 20.83,79.25 26.92,85.34 37.59,85.34 38.61,84.33 IC10.5 | v61.98,55.12 155.96,55.12 155.96,17.27 154.43,15.75 SV1.60
DBUS0
  Top 0.203: SV1.5 151.64,84.33 144.78,84.33 141.73,87.38 132.84,87.38 132.84,75.44 134.62,73.66 IC17.3 | IC2.13 113.79,39.88 117.6,43.69 117.6,71.63 115.82,73.41 IC16.3
  Bottom 0.203: 113.03,40.39 113.54,39.88 IC2.13 113.03,40.39 | 113.03,40.39 112.52,40.89 97.28,40.89 97.03,40.64 88.39,40.64 87.63,39.88 IC1.13 | 113.03,40.39 135.64,40.39 139.45,44.2 IC9.13 | 95.76,72.39 78.99,72.39 77.98,73.41 IC14.3 | 95.76,72.39 96.77,73.41 IC15.3 | 114.55,72.39 115.57,73.41 IC16.3 | 114.55,72.39 95.76,72.39 | 114.55,72.39 133.6,72.39 134.62,73.41 IC17.3
DBUS1
  Top 0.203: 141.48,67.82 141.48,69.34 134.87,75.95 IC17.4 | 141.48,67.82 141.48,48.77 139.7,46.99 IC9.14 | 141.48,67.82 152.15,67.82 152.91,68.58 152.91,80.52 151.89,81.53 SV1.7 | IC2.14 113.79,42.42 115.57,44.2 115.57,66.55 114.05,68.07 114.05,74.42 115.57,75.95 IC16.4
  Bottom 0.203: IC1.14 87.63,42.42 88.39,43.18 97.03,43.18 97.28,43.43 100.84,43.43 101.85,42.42 113.54,42.42 IC2.14 | IC14.4 77.98,75.95 78.74,75.18 87.88,75.18 88.14,74.93 90.17,74.93 91.19,75.95 96.77,75.95 IC15.4 97.03,75.95 97.54,75.95 98.55,74.93 109.22,74.93 109.47,75.18 114.81,75.18 115.57,75.95 IC16.4 115.82,75.95 116.59,75.95 117.6,74.93 128.27,74.93 128.52,75.18 133.86,75.18 134.62,75.95 IC17.4
DBUS2
  Top 0.203: IC1.15 87.63,44.96 93.47,44.96 93.47,80.26 96.77,83.57 IC15.7
  Bottom 0.203: 113.03,45.47 113.54,44.96 IC2.15 113.03,45.47 | 113.03,45.47 112.52,45.97 88.65,45.97 87.63,44.96 IC1.15 | 113.03,45.47 135.64,45.47 139.45,49.28 IC9.15 | SV1.9 151.64,79.25 139.19,79.25 134.87,83.57 IC17.7 134.62,83.57 133.6,82.55 117.6,82.55 116.59,83.57 115.82,83.57 IC16.7 115.57,83.57 114.81,82.8 109.47,82.8 109.22,82.55 98.55,82.55 97.54,83.57 97.03,83.57 IC15.7 96.77,83.57 91.19,83.57 90.17,82.55 88.14,82.55 87.88,82.8 78.74,82.8 77.98,83.57 IC14.7
DBUS3
  Top 0.203: SV1.11 151.64,76.71 142.24,86.11 134.87,86.11 IC17.8 | IC2.17 98.55,47.5 98.55,84.58 97.03,86.11 IC15.8
  Bottom 0.203: IC1.17 72.39,47.5 73.41,48.51 97.28,48.51 98.3,47.5 IC2.17 98.55,47.5 100.58,49.53 121.92,49.53 124.21,51.82 IC9.17 | IC14.8 77.98,86.11 78.74,85.34 87.88,85.34 88.14,85.09 90.68,85.09 91.69,86.11 96.77,86.11 IC15.8 97.03,86.11 97.54,86.11 98.55,85.09 109.22,85.09 109.47,85.34 114.81,85.34 115.57,86.11 IC16.8 115.82,86.11 116.59,86.11 117.6,85.09 133.6,85.09 134.62,86.11 IC17.8
DBUS4  (via drill 0.51)
  Top 0.203: IC2.18 98.55,44.96 v102.11,48.51 104.39,50.8 104.39,82.55 107.95,86.11 IC16.13
  Bottom 0.203: IC1.18 72.39,44.7 73.41,43.69 96.77,43.69 97.79,44.7 98.3,44.7 IC2.18 | v102.11,48.51 123.44,48.51 124.21,49.28 IC9.18 | IC14.13 70.36,86.36 71.37,87.38 87.63,87.38 88.65,86.36 89.15,86.36 IC15.13 89.41,86.36 90.17,86.36 91.19,87.38 98.04,87.38 98.3,87.12 107.19,87.12 107.95,86.36 IC16.13 108.2,86.36 108.71,86.36 109.73,87.38 117.09,87.38 117.35,87.12 126.24,87.12 127,86.36 IC17.13 127.25,86.36 127.76,86.36 128.78,87.38 136.14,87.38 137.92,85.6 155.45,85.6 155.45,78.74 154.69,77.98 153.16,77.98 153.16,75.44 151.89,74.17 SV1.13
DBUS5  (via drill 0.51)
  Top 0.203: 126.24,67.06 126.24,67.31 125.22,68.33 125.22,71.37 126.24,72.39 129.03,72.39 129.03,81.79 127.25,83.57 IC17.14 | 126.24,67.06 126.24,48.77 124.46,46.99 IC9.19 | 126.24,67.06 v134.62,67.06 | IC2.19 98.55,42.42 104.9,48.77 104.9,80.52 107.95,83.57 IC16.14
  Bottom 0.203: v134.62,67.06 147.32,67.06 151.64,71.37 SV1.15 | IC1.19 72.39,42.16 73.41,41.15 96.77,41.15 97.79,42.16 98.3,42.16 IC2.19 | IC14.14 70.36,83.82 71.37,84.84 87.63,84.84 88.65,83.82 89.15,83.82 IC15.14 89.41,83.82 90.17,83.82 91.19,84.84 98.04,84.84 98.3,84.58 107.19,84.58 107.95,83.82 IC16.14 108.2,83.82 108.71,83.82 109.73,84.84 117.09,84.84 117.35,84.58 126.24,84.58 127,83.82 IC17.14
DBUS6  (via drill 0.51)
  Top 0.203: IC2.20 98.55,39.88 v102.11,43.43 105.41,46.74 105.41,73.41 107.95,75.95 IC16.17 | v143.51,77.22 151.64,69.09 SV1.17
  Bottom 0.203: IC1.20 72.39,39.62 73.41,38.61 96.77,38.61 97.79,39.62 98.3,39.62 IC2.20 | v102.11,43.43 123.44,43.43 124.21,44.2 IC9.20 | IC14.17 70.36,76.2 71.37,77.22 87.63,77.22 88.65,76.2 89.15,76.2 IC15.17 89.41,76.2 90.17,76.2 91.19,77.22 98.04,77.22 98.3,76.96 107.19,76.96 107.95,76.2 IC16.17 108.2,76.2 108.71,76.2 109.73,77.22 117.09,77.22 117.35,76.96 126.24,76.96 127,76.2 IC17.17 127.25,76.2 127.76,76.2 128.78,77.22 v143.51,77.22
DBUS7
  Top 0.203: IC9.21 124.21,41.91 122.43,43.69 122.43,69.34 126.49,73.41 127,73.41 IC17.18 | IC2.21 98.55,37.34 105.92,44.7 105.92,71.37 107.95,73.41 IC16.18
  Bottom 0.203: SV1.19 151.89,66.55 153.16,67.82 153.16,72.9 137.92,72.9 136.14,74.68 128.78,74.68 127.76,73.66 127.25,73.66 IC17.18 127,73.66 126.24,74.42 117.35,74.42 117.09,74.68 109.73,74.68 108.71,73.66 108.2,73.66 IC16.18 107.95,73.66 107.19,74.42 98.3,74.42 98.04,74.68 90.68,74.68 89.66,73.66 89.41,73.66 IC15.18 89.15,73.66 88.65,73.66 87.63,74.68 71.37,74.68 70.36,73.66 IC14.18 | IC1.21 72.39,37.08 73.41,36.07 90.17,36.07 91.19,37.08 98.3,37.08 IC2.21
GND  (via drill 0.51)
  Top 0.203: 20.98,61.16 IC21.7 20.83,61.21 20.83,73.91 IC13.1 | IC18.15 49.28,22.35 51.05,24.13 51.05,25.4 49.28,27.18 IC18.13 | IC12.4 38.61,16.76 36,16.76 | IC12.5 38.61,19.3 36,19.3 | IC18.2 56.64,12.19 54,12.19 | IC18.8 56.64,27.43 54,27.43 | IC18.4 56.64,17.27 54,17.27 | v9.91,19.56 9.91,23.62 10.92,24.64 13.46,24.64 v13.46,25.65 | v23.88,26.92 26.92,29.97 26.92,50.04 29.72,52.83 30.99,52.83 IC19.11
  Top 1.27: IC21.7 19.62,60.62 18,59 18,41.73 C8.2 | IC19.7 37.62,60.62 36,59 36,41.73 C5.2 | IC20.7 55.62,60.62 54,59 54,41.73 C7.2 | IC12.8 36.89,26.89 36,26 36,19.3 36,16.76 36,5.27 C15.2 | IC18.10 55.43,32.43 54,31 54,27.43 54,17.27 54,12.19 54,5.27 C14.2 | IC1.16 82.32,47.32 80,45 80,5.73 C1.2 | IC2.16 109.32,47.32 107,45 107,6.73 C2.2 | IC9.16 136.32,51.94 134,49.62 134,7.73 C3.2 | IC13.8 20.81,94.46 C6.2 | IC10.8 38.81,94.46 C4.2 | IC11.8 56.81,94.46 C9.2 | IC14.10 77.81,94.46 C10.2 | IC15.10 96.81,94.46 C11.2 | IC16.10 115.81,94.46 C12.2 | IC17.10 134.81,94.46 C13.2
  Bottom 0.203: IC18.17 49.28,17.27 56.64,17.27 IC18.4 | IC18.11 49.28,32.51 49.28,38 | IC18.13 49.28,27.43 56.64,27.43 IC18.8 | v9.91,19.56 8.13,19.56 8.06,19.49 | v13.46,25.65 14.73,26.92 v23.88,26.92
  Bottom 1.27: SV1.1 SV1.3 | SV1.1 SV1.2 SV1.4 | SV1.1 147.63,89.37 145,92 145,97 143,98.49 133,98.49 | 19,98.49 13,98.49 10,96 10,92 5,88 5,38 | 19,98.49 37,98.49 | 37,98.49 55,98.49 | 55,98.49 76,98.49 | 76,98.49 95,98.49 | 95,98.49 114,98.49 | 114,98.49 133,98.49 | 5,26 5,15 8,12 14,12 17,9 17,5 20,2 36,2 | 5,26 5,38 | 36,2 54,2 | 54,2 79,2 | 79,2 105,2 | 105,2 133,2 133,3.27 C3.2 | C7.2 53.27,39.27 52,38 49.28,38 35,38 | 5,38 17,38 | 17,38 35,38 | C13.2 133.27,98.22 133,98.49 | C12.2 114.27,98.22 114,98.49 | C11.2 95.27,98.22 95,98.49 | C9.2 55.27,98.22 55,98.49 | C6.2 19.27,98.22 19,98.49 | C5.2 35.27,38.27 35,38 | C8.2 17.27,38.27 17,38 | JP1.8 5.19,25.81 5,26 | C4.2 37.27,98.22 37,98.49 | C10.2 76.27,98.22 76,98.49 | C15.2 36.27,2.27 36,2 | C14.2 54.27,2.27 54,2 | C1.2 79.27,2.27 79,2 | C2.2 105.27,2.27 105,2
  pour Bottom (isolate 0.406, no thermals): 0,100 160,100 160,0 0,0
MEMSEG  (via drill 0.51)
  Top 0.203: v40.13,28.96 34.04,35.05 v34.04,64.01 v34.04,72.9 34.04,73.66 36.83,76.45 36.83,84.84 38.61,86.61 IC10.6 | v142.49,62.99 142.49,39.88 152.91,39.88 154.18,38.61 SV1.42
  Bottom 0.203: v40.13,28.96 45.72,23.37 50.29,23.37 50.8,22.86 56.13,22.86 56.64,22.35 IC18.6 | v34.04,72.9 24.38,72.9 20.83,76.45 IC13.2 | v142.49,62.99 141.48,64.01 v34.04,64.01
N$1  (via drill 0.51)
  Top 0.203: v25.91,60.71 v25.91,79.5
  Bottom 0.203: v25.91,60.71 20.83,55.63 IC21.5 | v25.91,79.5 27.94,81.53 30.99,81.53 IC10.13 31.24,81.79 32.26,82.8 55.63,82.8 56.64,81.79 IC11.4
N$2
  Top 0.203: IC20.4 56.9,52.83 58.67,51.05 58.67,47.24 IC20.1
  Bottom 0.203: IC19.2 38.86,47.75 40.13,46.48 55.63,46.48 56.64,45.47 IC20.1
N$3
  Bottom 0.203: 21.84,49.02 20.83,48.01 IC21.2 | 21.84,49.02 52.32,49.02 53.34,48.01 56.64,48.01 IC20.2 | 21.84,49.02 10.92,49.02 10.92,84.33 11.94,85.34 17.02,85.34 20.57,81.79 IC13.4
N$4  (via drill 0.51)
  Top 0.203: IC21.1 20.83,45.47 22.61,47.24 22.61,82.3 20.83,84.07 IC13.5 | v59.18,45.47 59.18,53.09 56.9,55.37 IC20.5
  Bottom 0.203: v59.18,45.47 57.91,44.2 21.84,44.2 20.83,45.21 IC21.1
N$5
  Top 0.203: IC11.15 49.02,76.45 47.24,74.68 47.24,73.66 48.01,72.9 62.48,72.9 62.48,83.57 70.1,91.19 IC14.11
N$6  (via drill 0.51)
  Top 0.203: v47.24,90.17 47.24,81.03 49.02,79.25 IC11.14
  Bottom 0.203: v47.24,90.17 47.75,90.68 53.34,90.68 55.63,92.96 106.43,92.96 107.95,91.44 IC16.11
N$7  (via drill 0.51)
  Top 0.203: v50.55,93.47 51.05,92.96 51.05,83.57 49.28,81.79 IC11.13 | v86.61,93.98 89.15,91.44 IC15.11
  Bottom 0.203: v50.55,93.47 51.05,93.98 v86.61,93.98
N$8
  Bottom 0.203: IC11.12 49.28,84.33 55.63,90.68 67.06,90.68 68.83,92.46 104.9,92.46 107.19,90.17 112.27,90.17 114.55,92.46 125.98,92.46 127,91.44 IC17.11
N$9  (via drill 0.51)
  Top 0.203: v76.71,53.09 77.72,54.1 77.72,68.33 IC14.1
  Bottom 0.203: v76.71,53.09 59.44,53.09 IC20.3
N$10  (via drill 0.51)
  Top 0.203: v95.5,60.96 96.77,62.23 96.77,68.33 IC15.1
  Bottom 0.203: v95.5,60.96 59.69,60.96 IC20.6
N$11  (via drill 0.51)
  Top 0.203: v28.19,76.2 28.19,79.25 20.83,86.61 IC13.6
  Bottom 0.203: v28.19,76.2 29.21,75.18 35.56,75.18 45.47,65.28 112.52,65.28 115.57,68.33 IC16.1
N$12  (via drill 0.51)
  Top 0.203: v29.21,71.37 29.21,80.77 20.83,89.15 IC13.7
  Bottom 0.203: v29.21,71.37 35.81,64.77 131.06,64.77 134.62,68.33 IC17.1
N$13
  Top 0.203: IC20.8 49.28,60.45 52.07,57.66 52.07,14.99 49.28,12.19 IC18.19
  Bottom 0.203: IC18.19 49.28,11.94 51.56,9.65 56.64,9.65 IC18.1
N$14
  Bottom 0.203: IC21.3 20.83,50.55 27.18,56.9 48.01,56.9 IC20.9
N$15  (via drill 0.51)
  Top 0.203: IC12.15 31.24,11.68 35.05,15.49 35.05,26.42 36.58,27.94 44.96,27.94 44.96,49.28 46.74,51.05 49.02,51.05 49.02,50.55 IC20.12 51.05,52.32 51.05,56.64 48.26,56.64 47.24,57.66 47.24,58.17 v42.42,62.99
  Bottom 0.203: v42.42,62.99 26.67,62.99 13.21,76.45 IC13.15
N$16  (via drill 0.51)
  Top 0.203: v26.42,22.86 19.05,30.23 19.05,56.39 20.57,57.91 IC21.6
  Bottom 0.203: v26.42,22.86 37.59,22.86 38.61,21.84 IC12.6
N$17  (via drill 0.51)
  Top 0.203: v46.99,50.04 49.02,48.01 IC20.13
  Bottom 0.203: v46.99,50.04 41.66,50.04 38.86,52.83 IC19.4
PBUS15  (via drill 0.51)
  Top 0.203: v141.48,12.95 141.48,17.02 139.7,18.8 IC9.3 | IC15.2 96.77,70.87 94.49,68.58 94.49,10.67 93.22,9.4 93.22,8.89 93.98,8.13 96.52,8.13 96.52,9.91 98.3,11.68 IC2.31
  Bottom 0.203: 95.76,69.85 78.99,69.85 77.98,70.87 IC14.2 | 95.76,69.85 96.77,70.87 IC15.2 | 114.55,69.85 115.57,70.87 IC16.2 | 95.76,69.85 114.55,69.85 | 114.55,69.85 133.6,69.85 134.62,70.87 IC17.2 | 73.15,10.92 73.41,10.67 96.77,10.67 97.79,11.68 98.3,11.68 IC2.31 98.55,11.68 111.51,11.68 112.52,10.67 139.19,10.67 v141.48,12.95 | 73.15,10.92 72.39,11.68 IC1.31 | 73.15,10.92 52.83,10.92 49.28,14.48 IC18.18
PBUS16  (via drill 0.51)
  Top 0.203: v51.05,16.26 51.05,17.78 49.28,19.56 IC18.16 | v135.38,12.19 139.45,16.26 IC9.2 | IC15.5 96.77,78.49 93.98,75.69 93.98,18.29 87.63,11.94 IC1.2
  Bottom 0.203: IC14.5 77.98,78.49 78.74,77.72 87.88,77.72 88.14,77.47 90.68,77.47 91.69,78.49 96.77,78.49 IC15.5 97.03,78.49 97.54,78.49 98.55,77.47 109.22,77.47 109.47,77.72 114.81,77.72 115.57,78.49 IC16.5 115.82,78.49 116.59,78.49 117.6,77.47 128.27,77.47 128.52,77.72 133.86,77.72 134.62,78.49 IC17.5 | v51.05,16.26 51.56,15.75 68.58,15.75 71.37,12.95 85.85,12.95 86.87,11.94 87.38,11.94 IC1.2 87.63,11.94 88.39,12.7 97.03,12.7 97.28,12.95 112.52,12.95 113.54,11.94 IC2.2 113.79,11.94 135.13,11.94 v135.38,12.19
PBUS17
  Top 0.203: IC1.30 72.39,14.48 74.68,16.76 74.68,77.98 77.72,81.03 IC14.6
  Bottom 0.203: IC2.30 98.3,14.22 97.79,14.22 96.77,13.21 86.36,13.21 86.11,13.46 73.15,13.46 72.39,14.22 IC1.30 72.14,14.48 70.61,14.48 70.61,17.78 65.02,23.37 55.88,23.37 55.37,23.88 50.04,23.88 49.28,24.64 IC18.14 | IC17.6 134.62,81.03 133.6,80.01 117.6,80.01 116.59,81.03 115.82,81.03 IC16.6 115.57,81.03 110.24,81.03 109.22,80.01 107.19,80.01 106.93,80.26 97.79,80.26 97.03,81.03 IC15.6 96.77,81.03 96.01,80.26 90.42,80.26 90.17,80.01 88.14,80.01 87.12,81.03 77.98,81.03 IC14.6 77.72,81.03 76.96,81.03 75.95,80.01 69.09,80.01 68.83,80.26 27.94,80.26 25.65,77.98 19.81,77.98 19.56,78.23 13.97,78.23 13.21,78.99 IC13.14
PBUS18  (via drill 0.51)
  Top 0.203: 82.55,22.1 85.85,18.8 85.85,10.92 87.38,9.4 IC1.1 | v81.53,23.11 82.55,22.1 | v11.43,36.58 11.43,80.01 12.95,81.53 IC13.13 | 82.55,22.1 82.55,45.97 88.65,45.97 92.96,50.29 92.96,84.84 96.77,88.65 IC15.9
  Bottom 0.203: IC14.9 77.98,88.65 78.74,87.88 87.88,87.88 88.14,87.63 90.68,87.63 91.69,88.65 96.77,88.65 IC15.9 97.03,88.65 97.54,88.65 98.55,87.63 109.22,87.63 109.47,87.88 114.81,87.88 115.57,88.65 IC16.9 115.82,88.65 116.59,88.65 117.6,87.63 128.27,87.63 128.52,87.88 133.86,87.88 134.62,88.65 IC17.9 | IC1.1 87.63,9.4 88.39,10.16 97.03,10.16 97.28,10.41 112.01,10.41 113.03,9.4 113.54,9.4 IC2.1 | v81.53,23.11 71.37,23.11 65.28,29.21 64.77,29.21 64.26,28.7 50.29,28.7 49.28,29.72 IC18.12 49.02,29.97 18.03,29.97 v11.43,36.58
PBUS19  (via drill 0.51)
  Top 0.203: v58.42,8.38 58.67,8.64 58.67,27.94 56.9,29.72 IC18.9 56.9,29.97 62.99,36.07 62.99,81.53 70.1,88.65 IC14.12
  Bottom 0.203: v58.42,8.38 39.37,8.38 38.86,8.89 IC12.1 | 88.14,89.92 71.37,89.92 70.36,88.9 IC14.12 | 88.14,89.92 89.15,88.9 IC15.12 | 88.14,89.92 98.04,89.92 98.3,89.66 107.19,89.66 107.95,88.9 IC16.12 108.2,88.9 111.76,88.9 112.78,89.92 125.98,89.92 127,88.9 IC17.12
PBUS20  (via drill 0.51)
  Top 0.203: v44.45,25.91 44.45,17.27 38.86,11.68 IC12.2 | v65.02,28.19 65.02,78.23 67.82,81.03 70.1,81.03 IC14.15
  Bottom 0.203: v44.45,25.91 55.63,25.91 56.64,24.89 IC18.7 56.9,24.89 60.2,28.19 v65.02,28.19 | IC14.15 70.36,81.28 71.37,82.3 87.63,82.3 88.65,81.28 89.15,81.28 IC15.15 89.41,81.28 89.66,81.28 90.68,82.3 98.04,82.3 98.3,82.04 107.19,82.04 107.95,81.28 IC16.15 108.2,81.28 108.71,81.28 109.73,82.3 117.09,82.3 117.35,82.04 126.24,82.04 127,81.28 IC17.15
PBUS21  (via drill 0.51)
  Top 0.203: v65.02,22.1 66.04,23.11 66.04,73.41 65.53,73.91 65.53,77.98 66.29,78.74 70.1,78.74 IC14.16
  Bottom 0.203: IC12.3 38.86,14.22 43.18,18.54 55.63,18.54 56.64,19.56 IC18.5 56.9,19.81 59.18,22.1 v65.02,22.1 | IC14.16 70.36,78.74 71.12,79.5 76.2,79.5 76.45,79.76 87.63,79.76 88.65,78.74 89.15,78.74 IC15.16 89.41,78.74 89.66,78.74 90.68,79.76 98.04,79.76 98.3,79.5 107.19,79.5 107.95,78.74 IC16.16 108.2,78.74 108.71,78.74 109.73,79.76 117.09,79.76 117.35,79.5 126.24,79.5 127,78.74 IC17.16

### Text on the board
Top: VCC
Bottom: GND
_tsilk: 74LS139N | 74LS138N | 74LS138N | IC13 | IC10 | IC11 | 74LS374N | 74LS374N | 74LS374N | 74LS374N | IC14 | IC15 | IC16 | IC17 | IC21 | IC19 | IC20 | Main Memory v1.1 | (C) D.Pilawa, 03.2011 | 74LS08N | 74LS04N | 74LS32N | IC18 | IC12 | JP1 | AM29F010 | 74LS138N | 74LS244N | 628512 | 628512 | IC1 | IC2 | IC9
